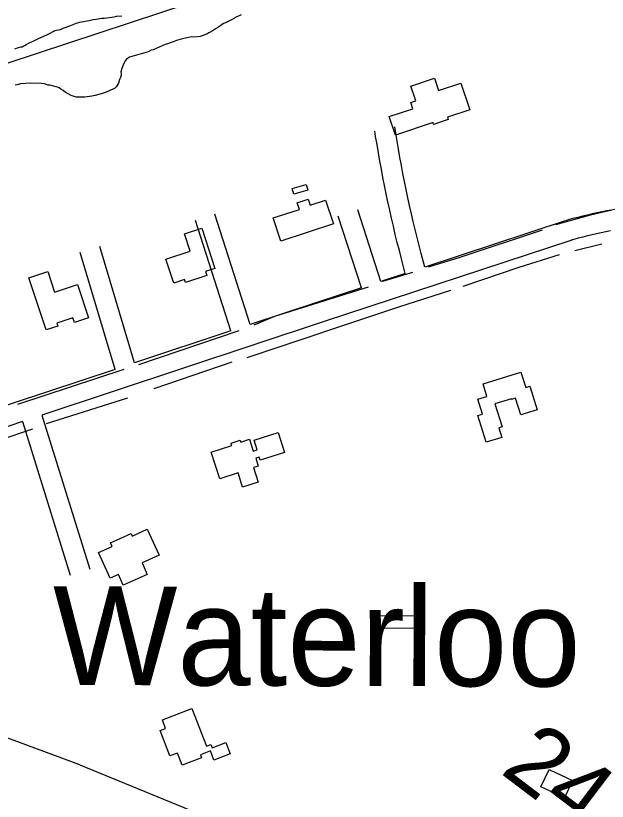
# Model space of a CAD drawing. Extents: x 3250478 to 3288318, y 788638 to 816472.
# Drawn here: x 3271685 to 3272554, y 797655 to 798809 of the extents above; entities that cross this region are included whole.
import ezdxf

# ---------------------------------------------------------------- set-up
doc = ezdxf.new("R2010")
doc.units = 0
for name, color, linetype in [('V-BLDG-OTLN', 7, 'Continuous'), ('V-ROAD-CNTR', 7, 'Continuous'), ('V-SITE-VEGE', 7, 'Continuous'), ('V-SURV-IDEN', 7, 'Continuous'), ('V-TOPO-GNAM-IDEN', 7, 'Continuous'), ('V-TOPO-SHOR', 7, 'Continuous'), ('V-UTIL-LINE', 7, 'Continuous')]:
    doc.layers.add(name, color=color, linetype=linetype)

msp = doc.modelspace()

# ---------------------------------------------------------------- linework, layer by layer
at = {"layer": 'V-BLDG-OTLN'}
for points in [[(3272352.3, 798670.8), (3272319.6, 798659.9), (3272320.6, 798656.6), (3272299.1, 798649.4), (3272298.2, 798652.1), (3272243, 798633.7), (3272233.9, 798660.9), (3272268.7, 798672.5), (3272265.6, 798681.6), (3272273, 798684), (3272265.7, 798705.7), (3272300.4, 798717.3), (3272306.4, 798699.3), (3272339.1, 798710.2)], [(3272091.2, 798555.3), (3272111.6, 798561.2), (3272114, 798552.6), (3272093.6, 798546.8)], [(3272151.7, 798503.2), (3272074.6, 798477.9), (3272063.4, 798512), (3272101.9, 798524.6), (3272098.7, 798534.2), (3272114.8, 798539.5), (3272117.7, 798530.8), (3272140.2, 798538.2)], [(3271958.3, 798497), (3271977.6, 798437.9), (3271963.7, 798433.3), (3271965.6, 798427.5), (3271934.3, 798417.3), (3271933, 798421.3), (3271917.1, 798416.1), (3271905.4, 798451.6), (3271941.1, 798463.3), (3271932.9, 798488.6)], [(3271704.2, 798424.2), (3271732, 798433.3), (3271741.9, 798403.1), (3271775.7, 798414.2), (3271791.8, 798365.3), (3271771.1, 798358.5), (3271768.9, 798365.2), (3271745.3, 798357.4), (3271746.8, 798353.1), (3271729.5, 798347.4)], [(3272364.3, 798221.6), (3272370.9, 798223.6), (3272364.1, 798245.5), (3272377.5, 798249.7), (3272371.7, 798268.1), (3272427.4, 798285.4), (3272434.4, 798262.8), (3272440.5, 798264.7), (3272451.3, 798230.1), (3272427.2, 798222.6), (3272419.6, 798247), (3272413.6, 798245.1), (3272413.3, 798246.1), (3272389.2, 798238.6), (3272399.7, 798205), (3272394.8, 798203.5), (3272399.2, 798189.5), (3272376.5, 798182.4)], [(3271984.7, 798128.5), (3271972, 798167.8), (3272002.5, 798177.6), (3272001.5, 798180.9), (3272014.9, 798185.3), (3272015.7, 798182.6), (3272028.5, 798186.7), (3272034, 798169.4), (3272039.7, 798171.2), (3272035.1, 798185.5), (3272070.4, 798196.9), (3272079.9, 798167.4), (3272044.2, 798155.9), (3272042.8, 798160.5), (3272037.7, 798158.9), (3272041.4, 798147.4), (3272034.3, 798145.1), (3272041.1, 798123.8), (3272018.3, 798116.4), (3272011.6, 798137.2)], [(3271806.8, 798020.1), (3271826.7, 798029.1), (3271824.3, 798034.5), (3271854.4, 798048.1), (3271856.1, 798044.3), (3271878.3, 798054.4), (3271895.5, 798016.4), (3271870.5, 798005), (3271878.1, 797988.2), (3271842.9, 797972.2), (3271835.8, 797987.9), (3271823.8, 797982.5)], [(3272276.5, 797927.8), (3272276.6, 797909), (3272219.2, 797908.7), (3272219.1, 797927.4)], [(3271943.9, 797790.9), (3271965.1, 797735.5), (3271971.7, 797738.1), (3271973.5, 797733.4), (3271993.9, 797741.2), (3272000.2, 797724.6), (3271976.1, 797715.3), (3271971, 797728.6), (3271956.4, 797723), (3271958.1, 797718.7), (3271929.5, 797707.8), (3271922.6, 797725.6), (3271911.5, 797721.3), (3271897.2, 797758.7), (3271905.2, 797761.8), (3271900.4, 797774.2)], [(3272491.2, 797659.7), (3272456.8, 797676), (3272468.9, 797701.5), (3272503.3, 797685.2)]]:
    msp.add_lwpolyline(points, close=True, dxfattribs=at)
at = {"layer": 'V-ROAD-CNTR'}
for points in [[(3272257.5, 798430.5), (3272251.8, 798452.1), (3272248.7, 798464), (3272245.7, 798475.9), (3272242.8, 798487.8), (3272239.9, 798499.7), (3272237.2, 798511.6), (3272234.5, 798523.6), (3272231.9, 798535.6), (3272229.4, 798547.6), (3272226.9, 798559.6), (3272224.6, 798571.6), (3272222.3, 798583.6), (3272220.1, 798595.7), (3272217.9, 798607.7), (3272215.9, 798619.8), (3272213.9, 798631.9), (3272212.7, 798639.6)], [(3272286.1, 798439.9), (3272280.8, 798459.8), (3272277.8, 798471.4), (3272274.8, 798483.1), (3272271.9, 798494.8), (3272269.1, 798506.6), (3272266.4, 798518.3), (3272263.8, 798530.1), (3272261.2, 798541.8), (3272258.7, 798553.6), (3272256.3, 798565.5), (3272254, 798577.3), (3272251.8, 798589.1), (3272249.6, 798601), (3272247.5, 798612.9), (3272245.5, 798624.7), (3272243.5, 798636.6), (3272242.1, 798646)], [(3272221.7, 798418.8), (3272187.5, 798523.8)], [(3272560.7, 798523.6), (3272553.5, 798522.3), (3272546.4, 798521), (3272539.3, 798519.5), (3272532.2, 798518), (3272525.1, 798516.3), (3272518, 798514.6), (3272510.9, 798512.9), (3272503.9, 798511), (3272496.9, 798509.1), (3272493.2, 798508)], [(3272029.7, 798355.3), (3271977.6, 798517.6)], [(3272193.3, 798409.4), (3272159, 798514.6)], [(3272001.2, 798345.9), (3271949, 798508.4)], [(3272492.6, 798507.8), (3272286.1, 798439.9)], [(3272559, 798492.9), (3272552.2, 798491.5), (3272545.4, 798490.1), (3272538.7, 798488.7), (3272531.9, 798487.1), (3272525.2, 798485.5), (3272518.4, 798483.8), (3272511.7, 798482.1), (3272505, 798480.2), (3272501.4, 798479.2)], [(3272502, 798479.3), (3272138.3, 798359.8), (3271723.2, 798222.1)], [(3271859.7, 798299), (3271808.5, 798469.9)], [(3271831.2, 798289.5), (3271779.8, 798461.3)], [(3272257.5, 798430.5), (3272221.7, 798418.8)], [(3272193.3, 798409.4), (3272128.9, 798388.3), (3272029.7, 798355.3)], [(3272001.2, 798345.9), (3271859.7, 798299)], [(3271831.2, 798289.5), (3271630.4, 798222.9), (3271482.7, 798174.4)], [(3271723.2, 798222.1), (3271793.8, 797996)], [(3271694.7, 798212.6), (3271639.8, 798194.4), (3271491.1, 798145.5)], [(3271694.7, 798212.6), (3271765.1, 797987.1)]]:
    msp.add_lwpolyline(points, dxfattribs=at)
at = {"layer": 'V-SITE-VEGE'}
for points in [[(3271683.6, 798760.8), (3271688.9, 798762.3), (3271692.2, 798763.4), (3271694.2, 798763.7), (3271700.4, 798766.8), (3271705.8, 798769.8), (3271710.3, 798771.7), (3271717.3, 798775.2), (3271731.8, 798781.6), (3271735.5, 798783.5), (3271740, 798786.2), (3271742.5, 798787.3), (3271744.5, 798788.1), (3271747.8, 798788.4), (3271750.7, 798789.1), (3271754.8, 798791), (3271764.6, 798794.3), (3271769.2, 798796.2), (3271773.7, 798798.5), (3271779, 798800), (3271792.5, 798802.4), (3271799, 798803.8), (3271803.1, 798804.1), (3271811.7, 798805.8), (3271814.9, 798805.7), (3271819, 798806), (3271829.6, 798807.7), (3271832.9, 798808.4), (3271841, 798809.3)], [(3272016, 798810.6), (3272007.8, 798806.8), (3272004.9, 798804.9), (3271998.3, 798801.4), (3271996.2, 798800.3), (3271994.5, 798799.1), (3271990.4, 798797.6), (3271988.4, 798796.1), (3271986.3, 798794.9), (3271981.7, 798791.8), (3271978.4, 798789.9), (3271975.1, 798787.6), (3271968.9, 798784.1), (3271966, 798782.2), (3271956.1, 798778.8), (3271946.8, 798777.9), (3271943.1, 798778), (3271938.6, 798777), (3271932.1, 798776), (3271928, 798774.9), (3271921.4, 798772.6), (3271916.5, 798770.8), (3271909.5, 798768.6), (3271904.6, 798766.7), (3271886.9, 798759.1), (3271884, 798758.4), (3271879.5, 798756.1), (3271859, 798750.3), (3271852, 798748.1), (3271849.2, 798746.6), (3271847.5, 798745.4), (3271845.8, 798743), (3271842.3, 798735.8), (3271841, 798731.8), (3271839.6, 798726.6), (3271839.9, 798724.1), (3271839.8, 798722.1), (3271838.9, 798718.5), (3271837.6, 798715.3), (3271835.8, 798710.1), (3271832.4, 798704.9), (3271829.9, 798702.5), (3271815.5, 798696.1), (3271810.5, 798694.2), (3271801.9, 798692.1), (3271797, 798691), (3271790.1, 798690), (3271786.4, 798689.3), (3271773.5, 798689.7), (3271766.6, 798692), (3271757.8, 798696.7), (3271754.7, 798699.3), (3271751.1, 798701.4), (3271748.7, 798703.1), (3271746.3, 798704), (3271735, 798707.2), (3271732.6, 798707.3), (3271727.4, 798709.1), (3271722.9, 798709.6), (3271706.7, 798710.1), (3271691.7, 798709), (3271686.8, 798707.9), (3271684.3, 798707.2)]]:
    msp.add_lwpolyline(points, dxfattribs=at)
at = {"layer": 'V-TOPO-SHOR'}
for p, q in [((3272506.8, 798464.4), (3272546.3, 798473.8)), ((3272268, 798431.7), (3272223.8, 798418.6)), ((3272012.6, 798346.2), (3271865.5, 798296)), ((3271888.3, 798261.5), (3272002.8, 798300.5)), ((3271843.6, 798289.5), (3271687.4, 798237.6)), ((3271729.9, 798209.9), (3271849.8, 798247.5))]:
    msp.add_line(p, q, dxfattribs=at)
for points in [[(3273123.9, 800882.5), (3273172, 800723.4), (3272419.8, 799692.2), (3272501.8, 799619.9), (3272641.5, 799513.8), (3272708.9, 799446.3), (3272839.1, 799378.8), (3272935.4, 799229.3), (3272916.1, 799157.1), (3272120.8, 798887.4), (3271537.5, 798694.8), (3270814.5, 798434.7), (3270101.1, 798198.7), (3269889, 798121.7), (3269648, 798059.1)], [(3272594.3, 798531.3), (3272527.8, 798515.7), (3272478.4, 798501.8)], [(3272458.8, 798494.1), (3272335.9, 798453.4), (3272291.3, 798439.9)], [(3272342.5, 798411.7), (3272425, 798439.5), (3272483.9, 798458.4)], [(3272202.8, 798410.2), (3272065.4, 798367), (3272034.9, 798354.2)], [(3272025.1, 798307), (3272248.2, 798381.2), (3272324.3, 798406.1)], [(3271508, 798130.9), (3271556.4, 798150.5), (3271660, 798185.3), (3271710.2, 798202.2)]]:
    msp.add_lwpolyline(points, dxfattribs=at)
at = {"layer": 'V-UTIL-LINE'}
for points in [[(3271779.1, 797708), (3269520, 798544.3), (3266561, 799643.4), (3262119.9, 801273.8), (3257978.5, 802819)], [(3271779.1, 797708), (3272434.5, 797439.4), (3273094.7, 796979.4), (3273232.3, 796851.7), (3274234.6, 796227.9)]]:
    msp.add_lwpolyline(points, dxfattribs=at)

# ---------------------------------------------------------------- texts
at = {"layer": 'V-SURV-IDEN'}
msp.add_text('2411+95.3', height=100, rotation=322.8286, dxfattribs=at).set_placement((3272395.3, 797697.1))
at = {"layer": 'V-TOPO-GNAM-IDEN'}
msp.add_text('Waterloo', height=145, rotation=359.8258, dxfattribs=at).set_placement((3271739.2, 797825.7))

doc.saveas('drawing.dxf')
